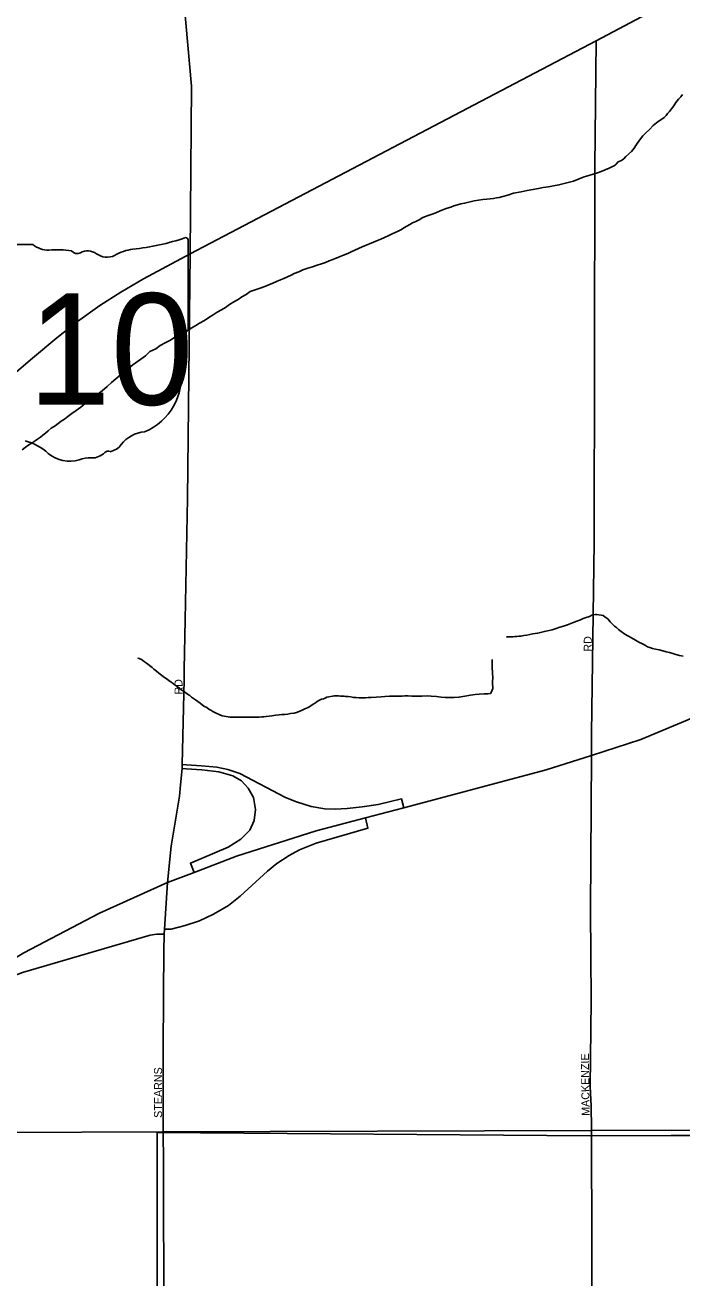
# Model space of a CAD drawing. Extents: x 2010165 to 2382125, y 1060529 to 1407316.
# Drawn here: x 2120255 to 2124358, y 1235321 to 1243150 of the extents above; entities that cross this region are included whole.
import ezdxf

# ---------------------------------------------------------------- set-up
doc = ezdxf.new("R2010")
doc.units = 0
for name, color, linetype in [('GM_X_City_Street', 7, 'Continuous'), ('GM_X_City_Street_Text', 7, 'Continuous'), ('GM_X_Corporation', 7, 'Continuous'), ('GM_X_County_Road', 7, 'Continuous'), ('GM_X_Interchange_Ramps', 7, 'Continuous'), ('GM_X_Interstate_Route', 7, 'Continuous'), ('GM_X_Minor_River', 7, 'Continuous'), ('GM_X_State_Location', 7, 'Continuous'), ('GM_X_State_Route', 7, 'Continuous'), ('GM_X_State_Shield', 7, 'Continuous'), ('GM_X_Township', 7, 'Continuous')]:
    doc.layers.add(name, color=color, linetype=linetype)

msp = doc.modelspace()

# ---------------------------------------------------------------- linework, layer by layer
at = {"layer": 'GM_X_City_Street'}
for points in [[(2121286.3, 1241720.4), (2121293.7, 1242768.4), (2121249.4, 1243280.5), (2121213.7, 1243422.6), (2121202.5, 1243737.1), (2121177.6, 1244066.8), (2121227.3, 1245313.7), (2121230.1, 1245922.2), (2121230.2, 1245940.7)], [(2123792.3, 1236226.9), (2123792.2, 1236242.4), (2123792.2, 1236253.5), (2123791.7, 1236396.4), (2123784.6, 1236518.5), (2123790.8, 1237054.1), (2123786.1, 1237621.4), (2123792.7, 1238586.2), (2123793.6, 1238724.5), (2123808.8, 1239916), (2123814.1, 1242264.2), (2123821.3, 1243051.7)], [(2121254.8, 1239434), (2121269, 1240191.2), (2121286.3, 1241720.4)], [(2121247.7, 1239061.8), (2121249.1, 1239126.5), (2121254.8, 1239434)], [(2121225.7, 1238403.5), (2121235.3, 1238505.8), (2121236.8, 1238530.1), (2121247.7, 1239061.8)], [(2121145.4, 1237792.8), (2121166.9, 1238018.7), (2121219.1, 1238332.4), (2121225.7, 1238403.5)], [(2121122.4, 1237363.4), (2121123.3, 1237468.9), (2121125.6, 1237500.1), (2121145.4, 1237792.8)], [(2121120.2, 1237099.8), (2121122.4, 1237363.4)], [(2121117.1, 1236730.6), (2121120.2, 1237099.8)], [(2121118.8, 1236045), (2121118.3, 1236234.2), (2121117, 1236717.3), (2121117.1, 1236730.6)]]:
    msp.add_lwpolyline(points, dxfattribs=at)
at = {"layer": 'GM_X_Corporation'}
msp.add_lwpolyline([(2132680.2, 1238887), (2124751.5, 1238922.2), (2124734, 1236210.6), (2124291.4, 1236212.5), (2123784.7, 1236210.1), (2121079.3, 1236231.2), (2121079, 1235091.9), (2120094.3, 1235126), (2120087.8, 1234155), (2113849.1, 1234218.1), (2113890.9, 1243217.2), (2116730.1, 1243190.3), (2116750.2, 1244175.2), (2120503.3, 1244150.8), (2120624.6, 1245916.3), (2121435.6, 1245924.1), (2121430.7, 1248710), (2122369.9, 1248724.5), (2122407.5, 1248826.9), (2123195.5, 1249602.9), (2123111, 1249688.7), (2124088.2, 1249725.4), (2124149.1, 1251538.9), (2132230.3, 1251466.2)], dxfattribs=at)
at = {"layer": 'GM_X_County_Road'}
for points in [[(2123800.2, 1232971.7), (2123796.3, 1234831.7), (2123792.3, 1236226.9)], [(2121121.5, 1235043), (2121118.8, 1236045)]]:
    msp.add_lwpolyline(points, dxfattribs=at)
at = {"layer": 'GM_X_Interchange_Ramps'}
for points in [[(2121235.3, 1238505.8), (2121260.6, 1238503.5), (2121358, 1238495.8), (2121464.9, 1238483.7), (2121553.3, 1238459.1), (2121607.2, 1238428.3), (2121649.2, 1238382.8), (2121681.6, 1238324.2), (2121693.3, 1238249.4), (2121685.2, 1238180), (2121659.1, 1238119.7), (2121603.2, 1238062.9), (2121524.4, 1238014.2), (2121287.3, 1237913), (2121310.9, 1237856)], [(2122621.1, 1238260), (2122606.5, 1238314.7), (2122460.2, 1238280), (2122360, 1238264.6), (2122267.6, 1238255), (2122192.5, 1238251.1), (2122127.1, 1238253), (2122042.3, 1238266.5), (2121949.9, 1238297.3), (2121880.6, 1238324.3), (2121595.6, 1238474.5), (2121520.6, 1238499.6), (2121453.2, 1238513), (2121356.6, 1238521.7), (2121262.4, 1238527.9), (2121236.8, 1238530.1)], [(2121125.6, 1237500.1), (2121168.2, 1237499.9), (2121254.8, 1237523), (2121343.4, 1237553.9), (2121432, 1237594.3), (2121526.3, 1237648.2), (2121597.6, 1237708), (2121768.9, 1237864), (2121826.7, 1237912.1), (2121903.7, 1237960.3), (2121969.2, 1237996.9), (2122073.2, 1238037.3), (2122396.6, 1238131.7), (2122380.2, 1238196.2)], [(2119876.6, 1237130.5), (2119907, 1237076.2), (2120020.7, 1237137.8), (2120113.1, 1237182.1), (2120238.2, 1237230.3), (2121035.4, 1237463.3), (2121077.7, 1237469.1), (2121123.3, 1237468.9)]]:
    msp.add_lwpolyline(points, dxfattribs=at)
at = {"layer": 'GM_X_Interstate_Route'}
for points in [[(2121145.4, 1237792.8), (2121310.9, 1237856), (2121575.6, 1237957.2), (2122073.3, 1238114.8), (2122380.2, 1238196.2), (2122621.1, 1238260), (2123509.8, 1238495.6), (2123792.7, 1238586.2), (2124101.8, 1238685.3), (2124559.1, 1238876.8), (2125038.8, 1239130), (2125324, 1239314), (2125630.5, 1239535.2), (2126524.3, 1240193.1), (2127428.9, 1240879.4), (2128036.8, 1241322.4), (2128857.9, 1241896), (2129564.2, 1242340.4), (2129645.8, 1242388.3), (2130001.7, 1242596.9), (2130394.6, 1242812.1), (2130737.7, 1243003.8), (2131133.3, 1243206.8)], [(2113848.7, 1234862), (2114396.6, 1234933.2), (2114491.1, 1234945.5), (2114674.5, 1234969.5), (2115864.7, 1235133.8), (2116441.6, 1235221), (2116674, 1235276), (2116937, 1235354.9), (2117252.6, 1235486.5), (2117575.2, 1235651.4), (2117690.8, 1235725.6), (2119876.6, 1237130.5), (2120247.7, 1237353.3), (2120718.7, 1237601.9), (2121145.4, 1237792.8)]]:
    msp.add_lwpolyline(points, dxfattribs=at)
at = {"layer": 'GM_X_Minor_River'}
for points in [[(2122585.4, 1241863.1), (2122605.4, 1241873.2), (2122621.4, 1241883.3), (2122639.5, 1241893.4), (2122657.5, 1241903.4), (2122675.5, 1241913.6), (2122695.6, 1241923.6), (2122715.6, 1241933.7), (2122739.6, 1241947.9), (2122773.7, 1241960), (2122797.7, 1241968.1), (2122819.8, 1241976.2), (2122843.8, 1241988.3), (2122867.9, 1241998.4), (2122891.9, 1242006.6), (2122914, 1242012.6), (2122934, 1242020.7), (2122956.1, 1242026.8), (2122976.1, 1242032.9), (2123000.2, 1242037), (2123034.3, 1242045.1), (2123060.3, 1242051.2), (2123086.4, 1242055.3), (2123114.5, 1242059.4), (2123138.6, 1242061.5), (2123160.6, 1242063.6), (2123180.7, 1242065.7), (2123198.7, 1242069.8), (2123216.8, 1242073.8), (2123238.8, 1242079.9), (2123270.9, 1242088), (2123305, 1242100.2), (2123353.1, 1242108.4), (2123391.2, 1242116.5), (2123427.3, 1242122.7), (2123461.4, 1242128.8), (2123491.5, 1242134.9), (2123523.6, 1242139), (2123555.7, 1242145.1), (2123589.7, 1242151.3), (2123680, 1242175.6), (2123716, 1242189.8), (2123746.1, 1242201.9), (2123776.2, 1242210.1), (2123804.2, 1242218.2), (2123830.3, 1242226.3), (2123852.3, 1242236.4), (2123878.4, 1242246.5), (2123902.4, 1242256.6), (2123920.5, 1242264.7), (2123934.5, 1242270.8), (2123944.5, 1242278.8), (2123958.5, 1242294.9), (2123980.5, 1242305), (2123994.5, 1242315.1), (2124006.5, 1242329.2), (2124042.5, 1242361.4), (2124058.5, 1242381.5), (2124074.5, 1242403.7), (2124092.4, 1242431.8), (2124114.4, 1242458), (2124134.4, 1242478.1), (2124154.4, 1242498.2), (2124178.4, 1242522.4), (2124198.4, 1242538.5), (2124216.4, 1242552.6), (2124232.5, 1242562.7), (2124246.5, 1242572.8), (2124258.5, 1242584.9), (2124268.5, 1242596.9), (2124280.4, 1242611), (2124292.4, 1242627.1), (2124306.4, 1242645.2), (2124320.4, 1242667.3), (2124336.4, 1242687.4), (2124350.4, 1242701.5), (2124360.4, 1242715.6)], [(2120236.3, 1240497), (2120256.3, 1240511.1), (2120278.4, 1240527.2), (2120298.4, 1240539.3), (2120318.4, 1240551.4), (2120332.4, 1240563.5), (2120350.4, 1240575.6), (2120366.4, 1240587.7), (2120382.4, 1240599.8), (2120398.4, 1240613.9), (2120418.4, 1240632), (2120442.5, 1240646.1), (2120462.5, 1240660.2), (2120480.5, 1240674.4), (2120500.5, 1240688.5), (2120522.5, 1240704.6), (2120546.6, 1240722.7), (2120574.6, 1240742.9), (2120602.6, 1240763), (2120630.6, 1240785.2), (2120660.6, 1240809.4), (2120694.7, 1240833.6), (2120736.7, 1240865.8), (2120766.7, 1240892), (2120794.7, 1240916.2), (2120822.7, 1240940.3), (2120848.7, 1240962.5), (2120874.7, 1240986.7), (2120902.8, 1241006.8), (2120928.8, 1241027), (2121006.8, 1241083.4), (2121034.8, 1241109.6), (2121070.9, 1241127.8), (2121098.9, 1241147.9), (2121129, 1241164.1), (2121159, 1241180.2), (2121189.1, 1241198.4), (2121219.1, 1241212.5), (2121245.1, 1241228.7), (2121271.2, 1241244.8), (2121297.2, 1241258.9), (2121321.2, 1241273.1), (2121345.3, 1241287.2), (2121375.3, 1241305.3), (2121403.3, 1241323.5), (2121429.4, 1241339.6), (2121455.4, 1241355.8), (2121481.4, 1241371.9), (2121507.5, 1241386), (2121531.5, 1241404.2), (2121559.5, 1241420.3), (2121585.6, 1241436.4), (2121609.6, 1241452.6), (2121635.6, 1241466.7), (2121661.6, 1241484.8), (2121697.7, 1241497), (2121723.8, 1241507.1), (2121751.8, 1241517.3), (2121777.9, 1241527.4), (2121801.9, 1241537.5), (2121826, 1241547.6), (2121850, 1241557.7), (2121872, 1241567.8), (2121894.1, 1241577.9), (2121916.1, 1241588), (2121936.2, 1241598.1), (2121964.2, 1241608.2), (2121990.3, 1241620.4), (2122020.3, 1241630.5), (2122050.4, 1241640.6), (2122078.4, 1241650.8), (2122106.5, 1241658.9), (2122130.6, 1241667), (2122154.6, 1241677.1), (2122176.7, 1241685.2), (2122198.7, 1241693.3), (2122222.7, 1241703.4), (2122244.8, 1241713.5), (2122270.8, 1241723.6), (2122290.9, 1241733.7), (2122361, 1241764), (2122385, 1241774.1), (2122407.1, 1241784.2), (2122431.1, 1241794.4), (2122455.2, 1241804.5), (2122477.2, 1241812.6), (2122499.3, 1241822.7), (2122527.3, 1241834.8), (2122547.3, 1241846.9), (2122567.4, 1241855), (2122585.4, 1241863.1)], [(2123948.5, 1239385.2), (2123936.4, 1239395.2), (2123926.3, 1239405.2), (2123910.2, 1239421.2), (2123894.1, 1239439.2), (2123878, 1239451.2), (2123865.9, 1239461.2), (2123825.8, 1239467.1), (2123815.8, 1239467.1), (2123795.7, 1239463), (2123779.7, 1239454.9), (2123759.6, 1239448.8), (2123741.6, 1239442.8), (2123723.6, 1239434.7), (2123701.5, 1239424.6), (2123673.5, 1239414.4), (2123643.4, 1239402.3), (2123617.4, 1239394.2), (2123595.3, 1239388.1), (2123571.3, 1239380), (2123547.2, 1239371.9), (2123519.1, 1239365.8), (2123499.1, 1239361.7), (2123475, 1239355.6), (2123457, 1239351.5), (2123440.9, 1239347.5), (2123424.9, 1239345.4), (2123406.8, 1239341.3), (2123388.8, 1239337.3), (2123370.7, 1239335.2), (2123352.7, 1239331.1), (2123338.6, 1239331.1), (2123326.6, 1239329.1), (2123314.6, 1239329), (2123300.5, 1239327), (2123286.5, 1239326.9), (2123276.4, 1239326.9), (2123262.4, 1239326.8), (2123262.4, 1239326.8)], [(2124366.5, 1239206), (2124342.4, 1239211.9), (2124320.3, 1239217.9), (2124300.2, 1239223.8), (2124280.1, 1239229.8), (2124260, 1239233.7), (2124238, 1239239.7), (2124215.8, 1239245.6), (2124191.8, 1239251.6), (2124173.7, 1239255.5), (2124157.6, 1239261.5), (2124143.6, 1239265.5), (2124129.5, 1239273.4), (2124111.4, 1239283.4), (2124089.3, 1239293.4), (2124067.1, 1239307.3), (2124043, 1239321.3), (2124020.9, 1239333.3), (2124000.8, 1239345.3), (2123978.7, 1239361.2), (2123960.6, 1239373.2), (2123948.5, 1239385.2)], [(2121472.1, 1238839.4), (2121462.1, 1238843.4), (2121452, 1238849.4), (2121440, 1238855.4), (2121427.9, 1238861.4), (2121415.8, 1238869.4), (2121401.8, 1238875.3), (2121389.7, 1238885.3), (2121371.6, 1238895.3), (2121347.5, 1238913.3), (2121333.4, 1238923.3), (2121319.3, 1238933.3), (2121307.2, 1238941.3), (2121295.2, 1238951.2), (2121283.1, 1238961.2), (2121269, 1238969.2), (2121256.9, 1238979.2), (2121244.9, 1238987.2), (2121230.8, 1238997.2), (2121218.7, 1239007.2), (2121204.6, 1239017.2), (2121192.6, 1239025.2), (2121180.5, 1239035.2), (2121166.4, 1239045.1), (2121152.3, 1239055.1), (2121136.2, 1239067.1), (2121120.1, 1239077.1), (2121106.1, 1239089.1), (2121090, 1239101.1), (2121075.9, 1239113.1), (2121059.8, 1239125.1), (2121047.7, 1239135.1), (2121013.5, 1239163.1), (2121001.4, 1239171), (2120991.4, 1239179), (2120981.3, 1239185), (2120967.2, 1239193), (2120961.2, 1239195), (2120961.2, 1239197)], [(2123172.6, 1239186.1), (2123172.7, 1239168), (2123172.7, 1239152), (2123172.8, 1239137.9), (2123172.8, 1239125.9), (2123174.8, 1239115.9), (2123174.9, 1239105.8), (2123174.9, 1239091.8), (2123177, 1239079.7), (2123175.1, 1239039.6), (2123175.1, 1239027.6), (2123177.2, 1239017.5), (2123177.2, 1239005.5), (2123169.3, 1238983.4), (2123161.3, 1238973.3), (2123145.2, 1238971.3), (2123123.2, 1238971.2), (2123091.1, 1238969.1), (2123067, 1238967), (2123036.9, 1238962.9), (2123000.8, 1238956.8), (2122964.7, 1238950.6), (2122934.6, 1238948.5), (2122908.5, 1238948.4), (2122880.4, 1238948.3), (2122854.3, 1238950.3), (2122824.2, 1238954.2), (2122792.1, 1238956.1), (2122766, 1238958), (2122733.9, 1238957.9), (2122711.8, 1238957.8), (2122689.8, 1238957.8), (2122669.7, 1238957.7), (2122647.6, 1238959.6), (2122627.6, 1238959.6), (2122609.5, 1238957.5), (2122591.5, 1238957.4), (2122573.4, 1238957.4), (2122553.3, 1238957.3), (2122531.2, 1238957.2), (2122501.2, 1238955.1), (2122479.1, 1238953.1), (2122416.9, 1238948.8), (2122398.8, 1238948.8), (2122380.8, 1238946.7), (2122362.7, 1238946.7), (2122342.7, 1238946.6), (2122322.6, 1238948.6), (2122306.5, 1238948.5), (2122290.5, 1238952.5), (2122272.4, 1238954.4), (2122258.3, 1238954.4), (2122248.3, 1238956.3), (2122236.3, 1238956.3), (2122224.2, 1238956.3), (2122212.2, 1238958.2), (2122202.1, 1238958.2), (2122186.1, 1238958.1), (2122176.1, 1238956.1), (2122152, 1238952), (2122140, 1238950), (2122130, 1238943.9), (2122117.9, 1238939.9), (2122105.9, 1238937.8), (2122089.9, 1238929.7), (2122079.9, 1238923.7), (2122067.9, 1238915.6), (2122053.8, 1238907.6), (2122039.8, 1238897.5), (2122023.8, 1238885.4), (2122001.8, 1238877.3), (2121985.7, 1238869.2), (2121971.7, 1238863.1), (2121955.7, 1238857.1), (2121935.6, 1238851), (2121913.6, 1238848.9), (2121895.5, 1238844.8), (2121877.5, 1238842.8), (2121859.4, 1238842.7), (2121841.4, 1238840.6), (2121821.3, 1238838.6), (2121797.2, 1238834.5), (2121779.2, 1238832.4), (2121761.1, 1238830.3), (2121747.1, 1238828.3), (2121733, 1238828.3), (2121717, 1238826.2), (2121700.9, 1238826.1), (2121684.9, 1238826.1), (2121636.7, 1238825.9), (2121618.7, 1238825.9), (2121596.6, 1238825.8), (2121580.5, 1238825.8), (2121566.5, 1238825.7), (2121548.4, 1238825.6), (2121534.4, 1238825.6), (2121524.3, 1238827.6), (2121510.3, 1238829.5), (2121498.3, 1238831.5), (2121486.2, 1238833.5), (2121472.1, 1238839.4)]]:
    msp.add_lwpolyline(points, dxfattribs=at)
at = {"layer": 'GM_X_State_Route'}
for points in [[(2121286.3, 1241720.4), (2123821.3, 1243051.7), (2124951.6, 1243650.8), (2125200.7, 1243789.5), (2125355.2, 1243865.2), (2125505, 1243961.4), (2125717.8, 1244122.2), (2125850.2, 1244223.1), (2125955.9, 1244300.3), (2126759.9, 1244908.9), (2127205.8, 1245253.4), (2127376.2, 1245375.2), (2127491.3, 1245446.4), (2127563.9, 1245485.8), (2127650.6, 1245526.8), (2128093.6, 1245700.3), (2128973.3, 1246056.5)], [(2113850.6, 1235339.5), (2114650.8, 1236082.2), (2115903.8, 1237299.6), (2116442.3, 1237786.1), (2117574.4, 1238760.5), (2118094.7, 1239202.2), (2118318.6, 1239381.7), (2118515.4, 1239556.9), (2118671.7, 1239689.2), (2118830, 1239821.4), (2118978.3, 1239941.6), (2119138.5, 1240083.9), (2119294.8, 1240208.2), (2119532.4, 1240412.7), (2119663.5, 1240522.8), (2119948.6, 1240769), (2120289.2, 1241059.1), (2120453.1, 1241196.2), (2120582.4, 1241298.7), (2120721.1, 1241398), (2120852, 1241481.6), (2120995.4, 1241565.1), (2121286.3, 1241720.4)]]:
    msp.add_lwpolyline(points, dxfattribs=at)
at = {"layer": 'GM_X_State_Shield'}
for p, q in [((2120303.2, 1241778.2), (2119895.5, 1241778.2)), ((2121273.9, 1241251.6), (2121273.9, 1241804.3)), ((2121273.8, 1241251.7), (2121273.9, 1241251.6))]:
    msp.add_line(p, q, dxfattribs=at)
for centre, radius, start, end in [((2120400.3, 1241900.8), 156.4, 231.61951, 271.11188), ((2120778, 1243218.7), 1476.4, 275.84447, 288.90645), ((2121258.5, 1241806.6), 15.5, 351.86209, 97.738), ((2120452.1, 1241184.9), 561.6, 80.48669, 94.98827), ((2120579.6, 1241767.7), 45.1, 219.79206, 297.10237), ((2120645.9, 1241645.6), 93.8, 54.46668, 119.14113), ((2120767, 1241813.1), 112.9, 233.85621, 294.82819), ((2120966.3, 1241455.4), 297, 97.34618, 120.76885), ((2121270.3, 1241211), 24, 107.94398, 210.33697), ((2121257.4, 1241249.5), 16.6, 289.60381, 7.73413), ((2121117.8, 1241141.2), 144, 340.03296, 23.64957), ((2121329.5, 1241020.3), 104.8, 136.8065, 186.92959), ((2120860.7, 1240950), 369.3, 292.30889, 8.98584), ((2121016.4, 1240406.7), 202.2, 94.40312, 142.57675), ((2120173.2, 1240228.6), 333.6, 47.18416, 75.83597), ((2120760.2, 1240600.9), 119.3, 282.87319, 323.27711), ((2120533.9, 1240637.1), 211.7, 230.70037, 286.29184), ((2120656.2, 1240271.8), 173.9, 85.69512, 111.20995), ((2120671.7, 1240558), 112.8, 268.77702, 315.54927), ((2120773.7, 1240455.7), 31.8, 65.75173, 132.64842)]:
    msp.add_arc(centre, radius, start, end, dxfattribs=at)
at = {"layer": 'GM_X_Township'}
msp.add_lwpolyline([(2113829.3, 1229946.4), (2113843.3, 1233474.2), (2113846.2, 1234211.5), (2117635, 1234187.5), (2120106.8, 1234174.6), (2120100.7, 1236231), (2121118.3, 1236234.2), (2123792.2, 1236242.4), (2124726.6, 1236245.3), (2124755.1, 1238927.6), (2127383.3, 1238913.2), (2132018.1, 1238887.9)], dxfattribs=at)

# ---------------------------------------------------------------- texts
at = {"layer": 'GM_X_City_Street_Text'}
for s, rotation, p in [('RD', 90, (2123794.5, 1239234.8)), ('RD', 90, (2121238.2, 1238966.4)), ('MACKENZIE', 90.70725, (2123781.3, 1236334.8)), ('STEARNS', 90, (2121110.5, 1236322))]:
    msp.add_text(s, height=50, rotation=rotation, dxfattribs=at).set_placement(p)
at = {"layer": 'GM_X_State_Location'}
for s in ['s', 'r']:
    msp.add_text(s, height=1, dxfattribs=at).set_placement((2120562.1, 1241161.4))
msp.add_text('10', height=1, rotation=0.00001, dxfattribs=at).set_placement((2120310.3, 1241088.7))
at = {"layer": 'GM_X_State_Shield'}
msp.add_text('10', height=696.1, dxfattribs=at).set_placement((2120272.1, 1240777.8))

doc.saveas('drawing.dxf')
